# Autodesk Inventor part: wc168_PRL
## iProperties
Shininess: 64.0
Length Units: 11272
Angle Units: 11279
Time Units: 11290
Mass Units: 11286
Length Display Precision: 3
Angle Display Precision: 2
Compacted: True
Part Number: wc168_PRL
Document SubType Name: Modeling
Created: 2004-08
Designer: John Blackburn
Manufacturer: Standard
Standards Organization: Custom
Material: Phenolic
Density: 0.0
Volumn: 0.0
Area: 0.0
PropertySet Name: Model Information
Control State: 0
Master: False
Checked Out: False
Author: John Blackburn
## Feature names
1. Revolution1
